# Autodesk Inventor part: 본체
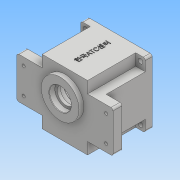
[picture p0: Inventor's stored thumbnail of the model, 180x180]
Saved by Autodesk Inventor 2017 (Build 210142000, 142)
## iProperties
Part Number: 본체
Material: 일반
Document SubType Name: Modeling
Designer: user
Density: 1 g/cm^3
Appearance: 기본값
Author: user
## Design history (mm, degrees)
sketch "스케치1"
  geometry: L1 (-70, -30)-(-70, 30); L2 (70, 30)-(70, -30); L3 (-33, -47)-(33, -47); L4 (33, 47)-(-33, 47); L5 (-70, 30)-(-33, 30); L6 (33, 30)-(70, 30); L7 (33, -47)-(33, -30); L8 (33, 30)-(33, 47); L9 (70, -30)-(33, -30); L10 (-33, 47)-(-33, 30); L11 (-33, -30)-(-33, -47); L12 (-33, -30)-(-70, -30); 1 further point
  constraints: 24 end point, 10 parallel, 4 perpendicular, 3 horizontal
  dimensions: "d0" = 140 distance of L1.end L2.start; "d1" = 60 distance of L1.start L1.end; "d2" = 66 distance of L4.end L4.start; "d3" = 94 distance of L4.start L3.end; "d4" = 140 distance of L2.end L1.start; "d5" = 66 distance of L3.start L3.end; "d6" = 37 distance of L2.end L7.end; "d7" = 37 distance of L11.start L1.start; "d8" = 17 distance of L6.start L4.start; "d9" = 33 horizontal distance of L6.start point (0, 0); "d10" = 30 vertical distance of L6.start point (0, 0); "d11" = 33 horizontal distance of point (0, 0) L3.start
extrude "돌출1" new body sketch "스케치1" distance "d12" = 13; taper "d13" = 0 deg
sketch "스케치3"
  geometry: L1 (-33, -47)-(33, -47); L2 (47, -30)-(47, 30); L3 (33, 47)-(-33, 47); L4 (-47, 30)-(-47, -30); L5 (-33, -30)-(-33, -47) reference; L6 (-33, 47)-(-33, 30) reference; L7 (-33, 30)-(-70, 30) reference; L8 (-70, -30)-(-33, -30) reference; L9 (-70, 30)-(-70, -30) reference; L10 (-70, -30)-(-33, -30) reference; L11 (-33, -30)-(-33, -47) reference; L12 (-33, -47)-(33, -47) reference; L13 (33, -47)-(33, -30) reference; L14 (33, -30)-(70, -30) reference; L15 (70, -30)-(70, 30) reference; L16 (70, 30)-(33, 30) reference; L17 (33, 30)-(33, 47) reference; L18 (33, 47)-(-33, 47) reference; L19 (-33, 47)-(-33, 30) reference; L20 (-33, 30)-(-70, 30) reference; 1 further point
  constraints: 9 point on line, 8 end point, 2 parallel, 1 horizontal, 1 perpendicular
  dimensions: "d17" = 94 distance between parallel lines of L4 L2; "d18" = 94 distance between parallel lines of L3 L1; "d19" = 14 distance from line of L4 L5.end
extrude "돌출3" join sketch "스케치3" distance "d20" = 67; taper "d21" = 0 deg
sketch "스케치4"
  geometry: L1 (-47, -47)-(47, -47); L2 (47, -47)-(47, 47); L3 (47, 47)-(-47, 47); L4 (-47, 47)-(-47, -47); L5 (-47, -47)-(47, 47); L6 (47, -47)-(-47, 47); 1 further point
  constraints: 12 end point, 2 midpoint, 2 parallel, 1 horizontal, 1 perpendicular
  dimensions: "d22" = 94 distance of L3.end L2.end; "d23" = 94 distance of L2.end L1.end
extrude "돌출4" join sketch "스케치4" distance "d24" = 10; taper "d25" = 0 deg
sketch "스케치5"
  geometry: C1 r 27.5 at (0, 11); 1 further point
  constraints: 1 centre point, 1 vertical alignment
  dimensions: "d26" = 55 diameter of C1; "d27" = 11 distance of point (0, 0) C1.centre
extrude "돌출5" join sketch "스케치5" distance "d28" = 7; taper "d29" = 0 deg
sketch "스케치6"
  geometry: C1 r 43 at (0, 0); 1 further point
  constraints: 1 centre point, 1 coincident
  dimensions: "d30" = 86 diameter of C1
extrude "돌출6" cut sketch "스케치6" distance "d31" = 9; taper "d32" = 0 deg
sketch "스케치7"
  geometry: C1 r 40 at (0, 0); 1 further point
  constraints: 1 centre point, 1 coincident
  dimensions: "d33" = 80 diameter of C1
extrude "돌출7" cut sketch "스케치7" distance "d34" = 62; taper "d35" = 0 deg
sketch "스케치8"
  geometry: C1 r 27.5 at (0, -11) reference; C2 r 21 at (0, -11); 1 further point
  constraints: 1 centre point, 1 coincident
  dimensions: "d36" = 42 diameter of C2
extrude "돌출8" join sketch "스케치8" distance "d37" = 7; taper "d38" = 0 deg
sketch "스케치9"
  geometry: C1 r 15 at (0, 20); C2 r 21 at (0, -11) reference; 1 further point
  constraints: 1 centre point, 1 vertical alignment
  dimensions: "d39" = 30 diameter of C1; "d40" = 20 distance of C1.centre point (0, 0)
extrude "돌출9" join sketch "스케치9" distance "d41" = 7; taper "d42" = 0 deg
sketch "스케치10"
  geometry: C1 r 27.5 at (0, 0) reference; C2 r 16 at (0, 0); 1 further point
  constraints: 1 centre point, 1 coincident
  dimensions: "d43" = 32 diameter of C2
extrude "돌출10" cut sketch "스케치10" distance "d44" = 8.3; taper "d45" = 0 deg
sketch "스케치11"
  geometry: C1 r 17.5 at (0, -11); A1 r 21 centre (0, -11) between (-8.978, 7.984) and (8.978, 7.984) reference; 1 further point
  constraints: 1 centre point, 1 coincident
  dimensions: "d46" = 35 diameter of C1
extrude "돌출11" cut sketch "스케치11" distance "d47" = 10; taper "d48" = 0 deg
sketch "스케치12"
  geometry: C1 r 17.5 at (0, 0) reference; C2 r 12.5 at (0, 0); 1 further point
  constraints: 1 centre point, 1 coincident
  dimensions: "d49" = 25 diameter of C2
extrude "돌출12" cut sketch "스케치12" distance "d50" = 10; taper "d51" = 0 deg
sketch "스케치13"
  geometry: C1 r 11 at (0, 20); A1 r 15 centre (0, 20) between (8.978, 7.984) and (-8.978, 7.984) reference; 1 further point
  constraints: 1 centre point, 1 coincident
  dimensions: "d52" = 22 diameter of C1
extrude "돌출13" cut sketch "스케치13" distance "d53" = 7; taper "d54" = 0 deg
sketch "스케치14"
  geometry: C1 r 11 at (0, 0) reference; C2 r 9.5 at (0, 0); 1 further point
  constraints: 1 centre point, 1 coincident
  dimensions: "d55" = 19 diameter of C2
extrude "돌출14" cut sketch "스케치14" distance "d56" = 3; taper "d57" = 0 deg
fillet "모깎기1" dims "d58" = 3
chamfer "모따기2" distance "d62" = 1; stored, may be unused: second distance "d63" = 2, angle "d64" = 45 deg
fillet "모깎기2" dims "d65" = 3
chamfer "모따기3" distance "d66" = 1; stored, may be unused: second distance "d67" = 2, angle "d68" = 45 deg
sketch "스케치15"
  geometry: L1 (36, 4)-(36.332, 4); L2 (36, -4)-(36.332, -4); A1 r 4 centre (36, 0) between (36, 4) and (36, -4); A2 r 40 centre (0, 0) between (39.799, 4) and (39.799, -4) reference; A3 r 40 centre (0, 0) between (39.278, 7.568) and (39.278, -7.568); A4 r 3 centre (36.332, 7) between (36.332, 4) and (39.278, 7.568); A5 r 3 centre (36.332, -7) between (39.278, -7.568) and (36.332, -4); 1 further point
  constraints: 12 point on circle, 6 tangent, 4 centre point, 4 end point, 2 equal radius, 2 horizontal, 2 point on line, 2 vertical alignment, 1 coincident, 1 horizontal alignment
  dimensions: "d69" = 8 diameter of A1; "d70" = 36 distance of point (0, 0) A1.centre; "d71" = 3 radius of A4 (derived)
extrude "돌출15" join sketch "스케치15" stored distance "d72" = 3; taper "d73" = 0 deg
sketch "스케치16"
  geometry: A1 r 4 centre (36, 0) between (36, 4) and (36, -4) reference; A2 r 4 centre (-36, 0) between (-36, -4) and (-36, 4) reference; 1 further point
hole "구멍1" sketch "스케치16" at (-36, 0), (36, 0) diameter "d74" = 3.242; stored, may be unused: countersink angle "d78" = 90 deg, drill point angle "d80" = 118 deg; dims "d75" = 7, "d76" = 4, "d77" = 2, "d79" = 9
sketch "스케치17"
  geometry: 2 further points
  dimensions: "d81" = 40 horizontal distance of point (-40, 40) point (0, 0); "d82" = 40 horizontal distance of point (-40, 40) point (0, 0)
hole "구멍2" sketch "스케치17" at (-40, 40) diameter "d83" = 7; stored, may be unused: countersink angle "d87" = 90 deg, drill point angle "d89" = 118 deg; dims "d84" = 7, "d85" = 4, "d86" = 2, "d88" = 9
sketch "스케치18"
  geometry: 2 further points
  dimensions: "d96" = 19 vertical distance of point (-60, 19) point (0, 0); "d97" = 60 horizontal distance of point (0, 0) point (-60, 19)
hole "구멍3" sketch "스케치18" at (-60, 19) diameter "d98" = 4.5; stored, may be unused: countersink angle "d102" = 90 deg, drill point angle "d104" = 118 deg; dims "d99" = 7, "d100" = 10, "d101" = 5, "d103" = 9
chamfer "모따기4" distance "d111" = 1; stored, may be unused: second distance "d112" = 2, angle "d113" = 45 deg
fillet "모깎기3" dims "d114" = 3
sketch "스케치19" dims "d0" = 140, "d1" = 60, "d2" = 66, "d3" = 94, "d4" = 140, "d5" = 66, "d6" = 37, "d7" = 37, "d8" = 17, "d9" = 33, "d10" = 30, "d11" = 33
  geometry: L1 (-11, 80)-(77, 80) reference; L2 (0, 0)-(66, 0) reference; 3 further points
  constraints: 1 midpoint, 1 vertical alignment, 1 other
  dimensions: "d115" = 40 distance from line of L1 point (33, 40)
feature "엠보싱1" sketch "스케치19" dims "d0" = 140, "d1" = 60, "d2" = 66, "d3" = 94, "d4" = 140, "d5" = 66, "d6" = 37, "d7" = 37, "d8" = 17, "d9" = 33, "d10" = 30, "d11" = 33, "d116" = 0.5, "d117" = 0
chamfer "모따기5" distance "d118" = 0.8; stored, may be unused: second distance "d119" = 2, angle "d120" = 30 deg
node "솔리드1"
mirror "미러1"
pattern_linear "직사각형 패턴1" dims "d92" = 80, "d95" = 80
pattern_linear "직사각형 패턴2" dims "d107" = 120, "d110" = 38
node "투영된 루프1"
